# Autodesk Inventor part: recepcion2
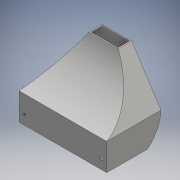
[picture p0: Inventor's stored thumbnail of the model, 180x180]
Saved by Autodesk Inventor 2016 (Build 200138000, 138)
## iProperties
Created: 2016-06
Part Number: recepcion2
Material: Generic
Document SubType Name: Modeling
Designer: yesi alvarez
Mass: 20.7888 g
Surface Area: 420.309 cm^2
Volume: 20.7888 cm^3
Density: 1 g/cm^3
Appearance: Default
Author: yesi alvarez
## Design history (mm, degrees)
sketch "Sketch2"
  geometry: L1 (0, 0)-(97, 0); L2 (97, 0)-(97, 60); L3 (97, 60)-(0, 60); L4 (0, 60)-(0, 0)
  constraints: 8 end point, 2 parallel, 1 horizontal, 1 perpendicular
  dimensions: "d11" = 97 distance of L3.end L2.end; "d12" = 60 distance of L2.end L1.end
workplane "Work Plane1"
sketch "Sketch3"
  geometry: L1 (32.333, 60)-(64.667, 60); L2 (64.667, 60)-(64.667, 45); L3 (64.667, 45)-(32.333, 45); L4 (32.333, 45)-(32.333, 60); 1 further point
  constraints: 8 end point, 2 parallel, 1 horizontal, 1 perpendicular
  dimensions: "d14" = 60 vertical distance of point (0, 0) L1.start; "d15" = 32.33333 horizontal distance of L1.start point (0, 0); "d16" = 32.33333 distance of L2.end L3.end; "d17" = 15 distance of L1.end L2.end
workplane "Work Plane2"
sketch "Sketch4"
  geometry: L1 (0, 0)-(97, 0); L2 (97, 0)-(97, 60); L3 (97, 60)-(0, 60); L4 (0, 60)-(0, 0)
  constraints: 8 end point, 2 parallel, 1 horizontal, 1 perpendicular
  dimensions: "d19" = 97 distance of L3.end L2.end; "d20" = 60 distance of L2.end L1.end
loft "Loft1" sketch "Sketch4" dims "d21" = 0, "d22" = 90 deg, "d23" = 0, "d24" = 90 deg
sketch "Sketch5"
  geometry: L1 (97, 0)-(97, 60) reference; L2 (0, 0)-(97, 0); L3 (97, 0)-(97, 60); L4 (97, 60)-(0, 60); L5 (0, 60)-(0, 0)
  constraints: 8 end point, 2 parallel, 1 horizontal, 1 perpendicular
  dimensions: "d25" = 97 distance of L4.end L1.end (derived); "d26" = 60 distance of L1.end L2.end (derived)
loft "Loft2" dims "d27" = 0, "d28" = 90 deg, "d29" = 0, "d30" = 90 deg
  node "Edges1"
workplane "Work Plane3"
sketch "Sketch6"
  geometry: L1 (67.082, 0)-(53.666, -26.833) reference; L2 (-22.361, -44.721)-(-8.944, -51.43) reference; L3 (53.666, -26.833)-(0, 0) reference; L4 (53.666, -26.833)-(-8.944, -51.43); A1 r 63.248 centre (41.946, -88.985) between (53.666, -26.833) and (-8.944, -51.43)
  constraints: 2 end point, 2 point on circle, 1 centre point
extrude "Extrusion2" cut sketch "Sketch6" distance "d31" = 100; taper "d32" = 0 deg
sketch "Sketch7"
  geometry: L1 (0, 60)-(0, 0) reference; L2 (30, 60)-(80, 60) reference; L3 (0, 45)-(0, 60); L4 (30, 60)-(30, 0) reference; L5 (30, 60)-(0, 60); A1 r 41.029 centre (31.746, 19.008) between (30, 60) and (0, 45)
  constraints: 4 end point, 2 point on circle, 1 centre point, 1 perpendicular, 1 point on line, 1 vertical
  dimensions: "d33" = 45 distance of L3.start L1.end
extrude "Extrusion3" cut sketch "Sketch7" distance "d34" = 100; taper "d35" = 0 deg
shell "Shell2" dims "d36" = 1
sketch "Sketch8"
  geometry: L1 (96, 0)-(96, 29.25) reference; L2 (1, 0)-(1, 29.25) reference; L3 (0, 0)-(97, 0) reference; L4 (97, 0)-(97, 30) reference; L5 (0, 0)-(0, 30) reference; C1 r 1.5 at (91, 10.53); C2 r 1.5 at (6, 10); 2 further points
  constraints: 2 centre point, 2 coincident
  dimensions: "d39" = 10 distance from line of point (6, 10) L3; "d40" = 3 diameter of C1; "d41" = 3 diameter of C2; "d48" = 6 distance from line of C1.centre L4; "d52" = 85 horizontal distance of point (6, 10) point (91, 10.53); "d53" = 6 distance from line of L5 C2.centre (derived)
extrude "Extrusion4" cut sketch "Sketch8" distance "d42" = 10; taper "d43" = 0 deg
thread "Thread1" dims "d44" = 10, "d45" = 0
thread "Thread2" dims "d46" = 10, "d47" = 0
body "Solid2"
